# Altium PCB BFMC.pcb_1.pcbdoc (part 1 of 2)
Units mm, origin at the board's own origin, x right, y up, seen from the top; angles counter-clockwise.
Board outline 115.66 x 88.65 mm, 2 copper layers (Top Layer, Bottom Layer); 106 components, 51 nets, 277 pads, 103 vias.
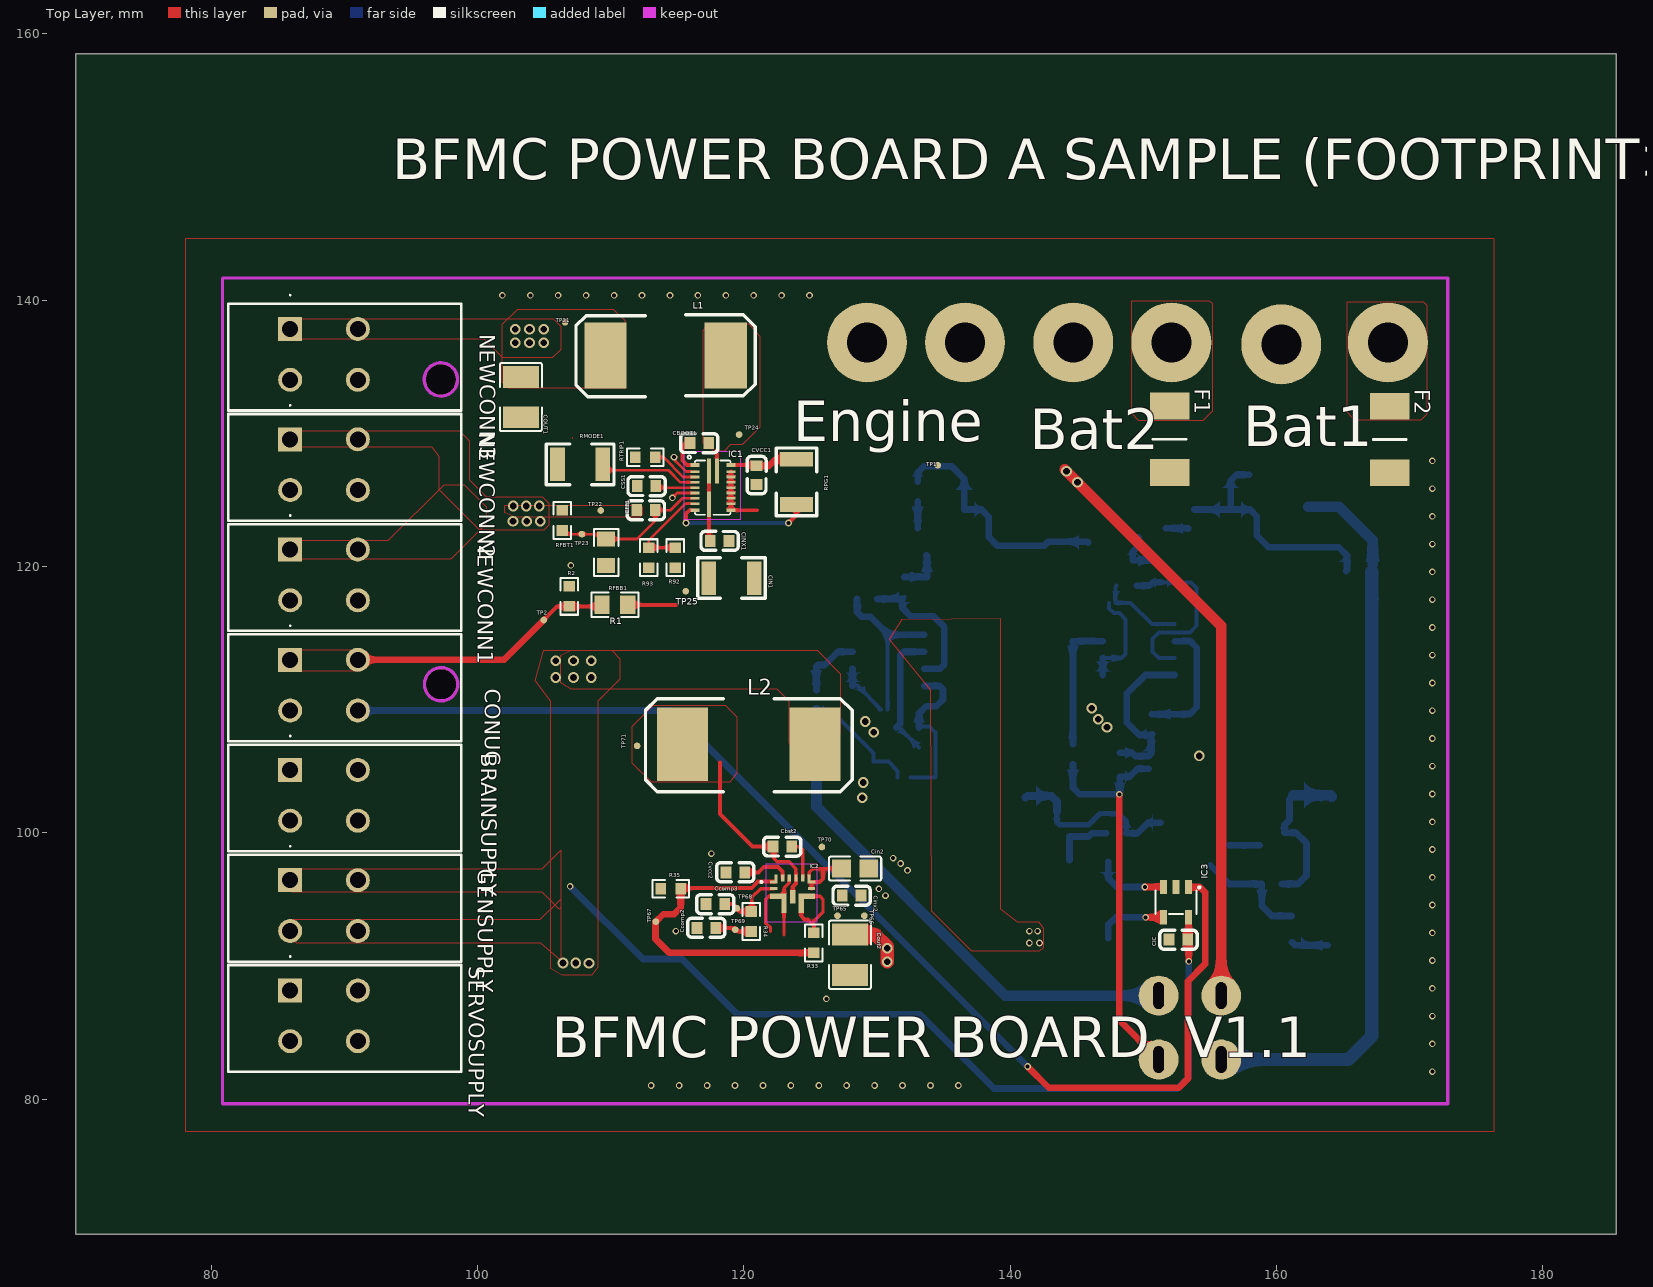
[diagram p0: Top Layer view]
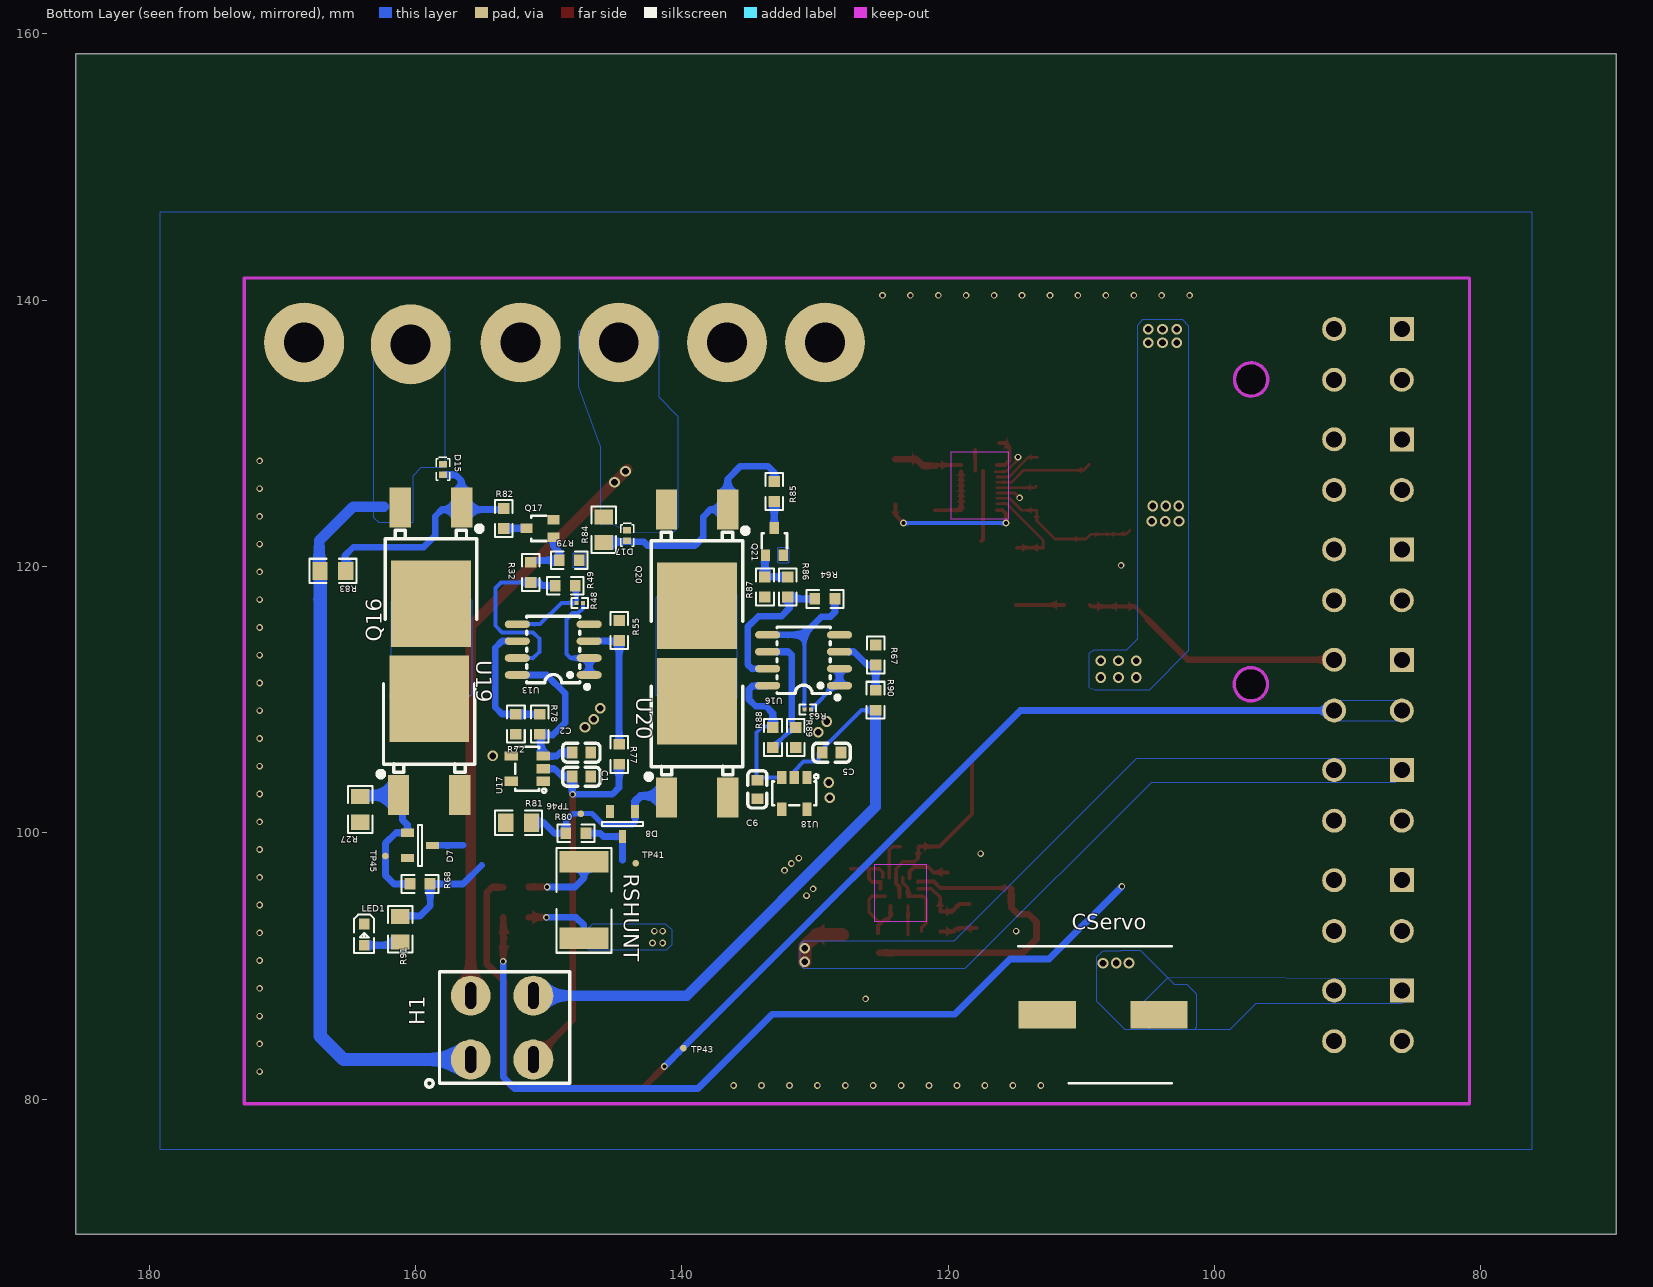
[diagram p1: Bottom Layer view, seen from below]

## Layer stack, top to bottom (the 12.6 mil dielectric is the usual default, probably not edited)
Top Layer: signal copper (thickness not stored)
Dielectric: dielectric 0.32, FR-4, Dk 4.8
Bottom Layer: signal copper (thickness not stored)

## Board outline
185.51,69.85 69.85,69.85 69.85,158.498 185.51,158.498
cut-out: 98.509,134.048 ccw(c97.259,134.048) 96.009,134.048 ccw(c97.259,134.048)
cut-out: 98.526,111.161 ccw(c97.276,111.161) 96.026,111.161 ccw(c97.276,111.161)

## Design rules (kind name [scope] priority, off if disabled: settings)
Clearance copperThickness1oz [All] p1: gap=0.178 ignorepadtopadclearanceinfootprint=FALSE except(0.102: Track-Track; 0.152: Track-SMDPad SMDPad-SMDPad Track-THPad SMDPad-THPad THPad-THPad Track-Via SMDPad-Via THPad-Via Via-Via Track-Fill SMDPad-Fill THPad-Fill Via-Fill Fill-Fill SMDPad-Region THPad-Region Via-Region Fill-Region Region-Region Track-Poly SMDPad-Poly THPad-Poly Via-Poly Fill-Poly Poly-Poly Track-Text SMDPad-Text THPad-Text Via-Text Fill-Text Region-Text Poly-Text Text-Text Track-Hole SMDPad-Hole THPad-Hole Via-Hole Fill-Hole Region-Hole Poly-Hole Text-Hole; 0.3: Track-Region Region-Poly Track-Sheet SMDPad-Sheet THPad-Sheet Via-Sheet Fill-Sheet Region-Sheet Poly-Sheet Text-Sheet Sheet-Hole)
Clearance copperThickness2oz [All] p1: gap=0.178 ignorepadtopadclearanceinfootprint=FALSE except(0.152: Track-SMDPad SMDPad-SMDPad Track-THPad SMDPad-THPad THPad-THPad Track-Via SMDPad-Via THPad-Via Via-Via Track-Fill SMDPad-Fill THPad-Fill Via-Fill Fill-Fill SMDPad-Region THPad-Region Via-Region Fill-Region Region-Region Track-Poly SMDPad-Poly THPad-Poly Via-Poly Fill-Poly Poly-Poly Track-Text SMDPad-Text THPad-Text Via-Text Fill-Text Region-Text Poly-Text Text-Text Track-Hole SMDPad-Hole THPad-Hole Via-Hole Fill-Hole Region-Hole Poly-Hole Text-Hole; 0.203: Track-Track; 0.3: Track-Region Region-Poly Track-Sheet SMDPad-Sheet THPad-Sheet Via-Sheet Fill-Sheet Region-Sheet Poly-Sheet Text-Sheet Sheet-Hole)
Clearance Supply-GND [All] p1: gap=0.178 ignorepadtopadclearanceinfootprint=FALSE except(0.5: Track-Track Track-SMDPad SMDPad-SMDPad Track-THPad SMDPad-THPad THPad-THPad Track-Via SMDPad-Via THPad-Via Via-Via Track-Fill SMDPad-Fill THPad-Fill Via-Fill Fill-Fill Track-Region SMDPad-Region THPad-Region Via-Region Fill-Region Region-Region Track-Poly SMDPad-Poly THPad-Poly Via-Poly Fill-Poly Region-Poly Poly-Poly Track-Text SMDPad-Text THPad-Text Via-Text Fill-Text Region-Text Poly-Text Text-Text Track-Sheet SMDPad-Sheet THPad-Sheet Via-Sheet Fill-Sheet Region-Sheet Poly-Sheet Text-Sheet Track-Hole SMDPad-Hole THPad-Hole Via-Hole Fill-Hole Region-Hole Poly-Hole Text-Hole Sheet-Hole)
DiffPairsRouting differentialPair [All] p1: maxuncoupledlength=10 maxlimit=5.9843 mostfreqgap=5.9843 toplayer_minwidth=5 toplayer_prefwidth=10 toplayer_maxwidth=100 bottomlayer_minwidth=5 bottomlayer_prefwidth=10 bottomlayer_maxwidth=100
PasteMaskExpansion pasteMaskExpansion [All] p1:
PlaneConnect innerPlane [All] p1: planeconnectstyle=Relief reliefexpansion=0.508 reliefentries=4 reliefconductorwidth=0.254 reliefairgap=0.254
PolygonConnect copperRegion [All] p1: connectstyle=Direct reliefentries=4 reliefconductorwidth=10 polygonreliefangle="90 Angle" airgapwidth=10
PolygonConnect copperRegion1 [All] p1: connectstyle=Relief reliefentries=4 reliefconductorwidth=10 polygonreliefangle="90 Angle" airgapwidth=10
PolygonConnect copperRegion2 [All] p1: connectstyle=Relief reliefentries=4 reliefconductorwidth=10 polygonreliefangle="90 Angle" airgapwidth=10
RoutingVias viaSize [All] p1: viastyle="Through Hole" holewidth=12.0078 minholewidth=11.811 maxholewidth=248.0314 width=24.0158 minwidth=19.685 maxwidth=393.7008
SolderMaskExpansion solderMaskExpansion [All] p1: useseparateexpansions=TRUE expansion=2.0079 expansionbottom=2.0079
Width copperThickness1oz [All] p1: maxlimit=100 minlimit=5 preferedwidth=10
Width copperThickness2oz [All] p1: maxlimit=100 minlimit=8 preferedwidth=10

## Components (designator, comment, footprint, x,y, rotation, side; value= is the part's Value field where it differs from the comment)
BRAINSUPPLY "switch" 1704498 85.944,104.723 r270 top
C1 "CAP_0201" C0603 147.54,104.22 r180 bottom
C2 "CAP_0201" C0603 147.54,106.02 r180 bottom
C5 "CAP_0201" C0603 128.76,106.02 r180 bottom
C6 "CAP_0201" C0603 134.34,103.26 r270 bottom
CBOOT1 "EMK105 B7104KVHF" C0603 116.664,129.265 r0 top
Cbst2 "CAP_0201" C0603 122.903,98.97 r0 top
Ccomp2 "CAP_0201" C0603 117.188,92.874 r0 top
Ccomp3 "CAP_0201" C0603 117.871,94.644 r0 top
CFF1 "C1005C0G1H220J" C0603 112.662,124.229 r0 top
CIC "C2012X7S1C106K" C0603 152.64,91.98 r180 top
CIN1 "GCJ31CC71E106K" R1206-1 119.086,119.132 r0 top
Cin2 "CAP_0201" c0805 128.364,97.319 r180 top
CINX1 "GCM188C71A225K" C0603 118.197,121.926 r0 top
Cinx2 "CAP_0201" C0603 128.11,95.287 r0 top
CONUC "switch" 1704498 85.944,113 r270 top
COUT1 "EMK325ABJ107MM-T" C1210 103.264,132.725 r270 top
Cout2 "CAP_0201" C1210 127.971,90.844 r90 top
CServo "GCM188C71A225K" CAPAE1030X1050N 108.377,86.347 r180 bottom
CSS1 "C1608X7R1H154K" C0603 112.697,126.041 r180 top
CVCC1 "GCM188C71A225K" C0603 120.964,126.865 r270 top
Cvcc2 "CAP_0201" C0603 119.371,97.044 r0 top
D7 "SZBZX84C18ET1G" SZBZX84C18ET1G 159.664,99.065 r270 bottom
D8 "SZBZX84C18ET1G" SZBZX84C18ET1G 144.464,100.665 r0 bottom
D15 "PZU6.8B2L,315" DFN1006-2L-RD 157.953,127.29 r270 bottom
D17 "PZU6.8B2L,315" DFN1006-2L-RD 144.11,122.337 r270 bottom
F1 "0451015.MRL" FUSC6127X294N 151.984,129.568 r270 top
F2 "0451015.MRL" FUSC6127X294N 168.512,129.541 r270 top
GENSUPPLY "switch" 1704498 85.944,96.447 r270 top
H1 "switch" M2021BB1W01 153.508,85.38 r0 bottom
IC1 "TPS548A28RWWR" TPS548B28RWWR 117.689,125.928 r0 top
IC2 "TPS61288RQQR" TPS61288RQQR 123.671,95.444 r0 top
IC3 "INA180A2QDBVRQ1" ina180a2qdbvrq1 152.46,94.8 r180 top
L1 "IHLP4040DZERR47M11" IHLP4040DZERR47M11 114.133,135.799 r0 top
L2 "L_0402" "dr127-3r3-r (l2)" 120.371,106.657 r0 top
LED1 "19-213/Y2C-CQ2R2L/3T(CY)" LED0603-RD-YELLOW 163.864,92.365 r270 bottom
NEWCONN1 "switch" 1704498 85.944,121.277 r270 top
NEWCONN2 "switch" 1704498 85.944,129.554 r270 top
NEWCONN3 "switch" 1704498 85.944,137.831 r270 top
Q16 "IPD50P04P4-13" pg-to252-3_l6.3-w6.5-p4.57-ls10.0-br-cw 158.842,120.813 r90 bottom
Q17 "BC846W" SOT-323-3_L2.2-W1.3-P1.30-LS2.2-BR 150.664,122.865 r180 bottom
Q20 "IPD50P04P4-13" pg-to252-3_l6.3-w6.5-p4.57-ls10.0-br-cw 138.864,120.665 r90 bottom
Q21 "BC846W" SOT-323-3_L2.2-W1.3-P1.30-LS2.2-BR 133.064,121.865 r270 bottom
R1 "MCR03..PFX1051" R0805_NEW 110.328,117.13 r0 top
R2 "MCR03...PFX7680" r0603_new 106.899,117.765 r90 top
R27 "MCR03..PFX1002" R0805_NEW 164.164,101.765 r270 bottom
R32 "MCR03..PFX1002" R0603 151.364,119.565 r90 bottom
R33 "MCR03..PFX1002" R0603 125.271,91.744 r90 top
R34 "MCR03..PFX1002" R0603 120.571,93.344 r90 top
R35 "MCR03..PFX1002" R0603 114.521,95.795 r180 top
R48 "Res_0603" R0201 147.664,117.265 r0 bottom
R49 "Res_0603" R0603 148.764,118.565 r0 bottom
R55 "Res_0603" R0603 144.72,115.2 r270 bottom
R63 "Res_0603" R0201 130.564,109.265 r0 bottom
R64 "Res_0603" R0603 129.264,117.565 r0 bottom
R67 "Res_0603" R0603 125.437,113.365 r270 bottom
R68 "Res_0603" R0603 159.664,96.165 r180 bottom
R72 "Res_0603" R0603 152.464,108.165 r270 bottom
R77 "Res_0603" R0603 144.72,105.9 r270 bottom
R78 "Res_0603" R0603 150.664,108.165 r270 bottom
R79 "Res_0603" R0603 148.464,120.465 r0 bottom
R80 "Res_0603" R0603 147.964,99.965 r180 bottom
R81 "MCR03..PFX1002" R0805_NEW 152.264,100.765 r0 bottom
R82 "Res_0603" R0603 153.381,123.607 r90 bottom
R83 "MCR03..PFX1002" R0805_NEW 166.208,119.67 r0 bottom
R84 "MCR03..PFX1002" R0805_NEW 145.864,122.765 r90 bottom
R85 "Res_0603" R0603 133.061,125.639 r90 bottom
R86 "MCR03..PFX1002" R0603 132.064,118.465 r270 bottom
R87 "Res_0603" R0603 133.764,118.465 r90 bottom
R88 "Res_0603" R0603 133.164,107.165 r270 bottom
R89 "Res_0603" R0603 131.464,107.165 r270 bottom
R90 "Res_0603" R0603 125.464,109.965 r90 bottom
R91 "Res_0603" R0805_NEW 161.164,92.765 r90 bottom
R92 "Res_0603" R0603 114.864,120.665 r270 top
R93 "Res_0603" R0603 112.864,120.665 r90 top
RFBB1 "SMM0204 50 10K 1 %" R0805 109.664,121.065 r270 top
RFBT1 "SMM0204 50 73K2 1 %" R0603 106.364,123.465 r270 top
RMODE1 "SMM0204 50 30K1 1 %" R1206-1 107.715,127.677 r180 top
RPG1 "SMM0204 50 30K1 1 %" R1206-1 123.964,126.365 r90 top
RSHUNT "WSLP25122L500FEA" "WSLP25122L000FEA BUN" 147.364,94.965 r270 bottom
RTRIP1 "SMM0204 50 7K32 1 %" R0603 112.606,128.214 r180 top
SERVOSUPPLY "switch" 1704498 85.944,88.17 r270 top
TP1 "Test-Point" Test-Point-0.5mm 134.569,127.607 r180 top
TP2 "Test-Point" Test-Point-0.5mm 104.98,115.987 r0 top
TP21 "Test-Point" Test-Point-0.5mm 106.588,138.349 r0 top
TP22 "Test-Point" Test-Point-0.5mm 109.268,124.212 r0 top
TP23 "Test-Point" Test-Point-0.5mm 107.847,122.434 r90 top
TP24 "Test-Point" Test-Point-0.5mm 119.651,129.911 r270 top
TP25 "Test-Point" Test-Point-0.5mm 115.651,118.146 r0 top
TP41 "Test-Point" Test-Point-0.5mm 143.472,97.723 r180 bottom
TP43 "Test-Point" Test-Point-0.5mm 139.89,83.841 r180 bottom
TP45 "Test-Point" Test-Point-0.5mm 162.264,98.265 r180 bottom
TP46 "Test-Point" Test-Point-0.5mm 147.591,101.439 r180 bottom
TP65 "Test-Point" Test-Point-0.5mm 127.039,93.784 r0 top
TP66 "Test-Point" Test-Point-0.5mm 129.062,93.782 r270 top
TP67 "Test-Point" Test-Point-0.5mm 113.401,93.335 r0 top
TP68 "Test-Point" Test-Point-0.5mm 119.486,94.335 r0 top
TP69 "Test-Point" Test-Point-0.5mm 119.364,92.733 r0 top
TP70 "Test-Point" Test-Point-0.5mm 125.871,98.944 r270 top
TP71 "Test-Point" Test-Point-0.5mm 111.994,106.536 r0 top
U13 "LT1490IS8#PBF" SO-8_L4.9-W3.9-P1.27-LS5.9-BL 149.664,113.765 r90 bottom
U16 "LT1490IS8#PBF" SO-8_L4.9-W3.9-P1.27-LS5.9-BL 130.864,112.965 r90 bottom
U17 "NCP715SN50T1G" TSOP-5_L3.0-W1.5-P0.95-BL 151.62,104.82 r90 bottom
U18 "NCP715SN50T1G" TSOP-5_L3.0-W1.5-P0.95-BL 131.564,102.965 r0 bottom
U19 "DMPH3010LK3-13" pg-to252-3_l6.3-w6.5-p4.57-ls10.0-br-cw 158.978,106.451 r270 bottom
U20 "DMPH3010LK3-13" pg-to252-3_l6.3-w6.5-p4.57-ls10.0-br-cw 138.864,106.265 r270 bottom

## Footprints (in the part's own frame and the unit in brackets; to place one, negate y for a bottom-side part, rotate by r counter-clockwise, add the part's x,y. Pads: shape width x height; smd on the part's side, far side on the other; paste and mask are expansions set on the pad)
1704498 [mm]
  rect 1.8x1.8 hole 1.2: 1(0,0)
  round 1.8 hole 1.2: 2(0,5.08) 3(3.81,0) 4(3.81,5.08)
  silkscreen extent -2.6,-4.65 6.11,12.85
C0603 [mm]
  rect 0.8x0.9 smd: 1(-0.7,0) 2(0.7,0)
  silkscreen extent -1.41,-0.71 1.39,0.72
c0805 [mm]
  rect 1.41x1.35 smd: 1(-1.03,0) 2(1.03,0)
  silkscreen extent -1.96,-0.9 1.96,0.9
C1210 [mm]
  rect 1.635x2.7 smd: 1(-1.517,0) 2(1.517,0)
  silkscreen extent -2.56,-1.58 2.56,1.58
CAPAE1030X1050N [mm]
  rect 4.3x2.05 smd: 1(-4.2,0) 2(4.2,0)
  silkscreen extent -6.35,-5.15 5.15,5.15
DFN1006-2L-RD [mm]
  rect 0.5x0.6 smd: 1(-0.4,0) 2(0.4,0)
  silkscreen extent -0.9,-0.5 0.8,0.5
"dr127-3r3-r (l2)" [mm]
  rect 3.85x5.5 smd: 1(-4.975,0) 2(4.975,0)
  silkscreen extent -7.75,-3.56 7.77,3.43
FUSC6127X294N [mm]
  rect 2.02x2.95 smd: 1(-2.5,0) 2(2.5,0)
  silkscreen extent 0,-1.24 0,1.24
IHLP4040DZERR47M11 [mil]
  rect 125x195 smd: 1(-177.5,2.5) 2(177.5,2.5)
  silkscreen extent -265,-120 265,122
ina180a2qdbvrq1 [mm]
  rect 0.532x1.07 smd: 1(-0.95,-1.135) 2(0,-1.135) 3(0.95,-1.135) 4(0.95,1.135) 5(-0.95,1.135)
  silkscreen extent -1.9,-1.25 1.53,0.88
LED0603-RD-YELLOW [mm]
  rect 0.8x0.8 smd: 1(-0.799,-0.003) 2(0.799,0.003)
  silkscreen extent -1.49,-0.75 1.39,0.76
M2021BB1W01 [mm]
  round 3 hole 0.8 slot 2 at 90 deg: 1(-2.35,-2.4) 2(2.35,-2.4) 3(-2.35,2.4) 4(2.35,2.4)
  silkscreen extent -5.08,-4.19 5.74,4.47
pg-to252-3_l6.3-w6.5-p4.57-ls10.0-br-cw [mm]
  rect 3x1.6 smd: 1(3.614,-2.299) 3(3.614,2.299)
  rect 6.5x6 smd: 2(-3.614,0.001)
  silkscreen extent -4.76,-3.83 2.24,3.43
R0201 [mm]
  rect 0.303x0.324 smd: 1(-0.242,0) 2(0.242,0)
  silkscreen extent -0.62,-0.39 0.62,0.39
R0603 [mm]
  rect 0.806x0.864 smd: 1(-0.753,0) 2(0.753,0)
  silkscreen extent -1.39,-0.66 1.39,0.66
r0603_new [mm]
  rect 0.806x0.864 smd: 1(-0.753,0) 2(0.753,0)
  silkscreen extent -1.39,-0.66 1.39,0.66
R0805 [mm]
  rect 1.133x1.377 smd: 1(-1,0) 2(1,0)
  silkscreen extent -1.76,-0.92 1.76,0.92
R0805_NEW [mm]
  rect 1.133x1.377 smd: 1(-0.966,0) 2(0.966,0)
  silkscreen extent -1.76,-0.92 1.76,0.92
R1206-1 [mm]
  rect 1.1x2.5 smd: 1(-1.7,0) 2(1.7,0)
  silkscreen extent -2.54,-1.52 2.54,1.52
SO-8_L4.9-W3.9-P1.27-LS5.9-BL [mm]
  oval 0.574x1.888 smd: 1(-1.905,-2.699) 2(-0.635,-2.699) 3(0.635,-2.699) 4(1.905,-2.699) 5(1.905,2.699) 6(0.635,2.699) 7(-0.635,2.699) 8(-1.905,2.699)
  silkscreen extent -2.94,-2.69 2.5,2
SOT-323-3_L2.2-W1.3-P1.30-LS2.2-BR [mm]
  rect 0.9x0.7 smd: 1(1.016,-0.66) 2(1.016,0.66) 3(-1.016,0)
  silkscreen extent -0.65,-0.95 0.48,0.95
SZBZX84C18ET1G [mm]
  rect 0.61x0.975 smd: 1(-0.95,-0.937) 2(0.95,-0.937)
  rect 0.523x0.975 smd: 3(0,0.937)
  silkscreen extent -1.54,-0.14 1.54,0.14
Test-Point-0.5mm [mm]
  round 0.5 smd: 1(0,0)
TPS548B28RWWR [mm]
  rect 0.7x0.3 smd: 1(-1.35,1.7) 9(-1.35,-1.7) 11(1.35,-1.7) 19(1.35,1.7)
  rect 0.7x0.2 smd: 2(-1.35,1.2) 3(-1.35,0.8) 4(-1.35,0.4) 5(-1.35,0) 6(-1.35,-0.4) 7(-1.35,-0.8) 8(-1.35,-1.2) 12(1.35,-1.2) 13(1.35,-0.8) 14(1.35,-0.4) 15(1.35,0) 16(1.35,0.4) 17(1.35,0.8) 18(1.35,1.2)
  rect 0.3x1.9 smd: 10(-0.3,-1.25) 20(0.3,1.25) 21(-0.3,1.25)
  silkscreen extent -1.9,-2.03 1.32,2.41
TPS61288RQQR [mm]
  rect 0.575x0.25 smd: 1(-1.413,0.875) 7(1.413,0.875)
  rect 0.55x0.25 smd: 2(-1.425,0.375) 6(1.425,0.375)
  rect 1.25x0.4 smd: 3(-1.075,-0.2) 5(1.075,-0.2)
  rect 0.4x1 smd: 4(0,-0.25)
  rect 0.25x0.55 smd: 8(0.75,1.175) 9(0.25,1.175) 10(-0.25,1.175) 11(-0.75,1.175)
  rect 0.225x0.45 smd: 12(-1.237,1.225) 15(1.237,1.225)
  rect 0.4x1.05 smd: 13(-0.65,-0.925) 14(0.65,-0.925)
  silkscreen extent -2.4,0.83 -2.3,0.92
TSOP-5_L3.0-W1.5-P0.95-BL [mm]
  rect 0.7x1 smd: 1(-0.95,-1.2) 2(0,-1.2) 3(0.95,-1.2) 4(0.95,1.2) 5(-0.95,1.2)
  silkscreen extent -1.8,-1.42 1.65,0.89
"WSLP25122L000FEA BUN" [mm]
  rect 1.6x3.68 smd: 1(-2.875,0) 2(2.875,0)
  silkscreen extent -3.91,-2.07 3.96,2.07

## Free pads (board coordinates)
  round 6 hole 3: 22(129.251,136.815) 22(136.617,136.815) 22(144.745,136.815) 22(152.111,136.815) 22(160.366,136.688) 22(168.367,136.815)

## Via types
v1: diameter 0.5, hole 0.3, Top Layer to Bottom Layer, 70 vias
v2: diameter 0.8, hole 0.5, Top Layer to Bottom Layer, 33 vias

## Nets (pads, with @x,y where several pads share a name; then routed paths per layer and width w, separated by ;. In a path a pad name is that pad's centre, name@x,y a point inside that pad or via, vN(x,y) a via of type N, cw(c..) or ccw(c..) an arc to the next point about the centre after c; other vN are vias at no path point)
$1N1788: D8.1 R80.1 R81.1 TP46.1 U20.1 | length 13.8
  Bottom Layer w0.4: D8.1@143.514,101.602 143.514,100.806 143.7,100.62 145.92,100.62 146.762,101.462 147.567,101.462 TP46.1@147.591,101.439 148.161,101.439 148.717,100.883 R80.1@148.717,99.965
  Bottom Layer w0.5: R80.1@148.717,99.965 149.551,99.965 150.351,100.765 R81.1@151.297,100.765
  Bottom Layer w0.6: U20.1@141.163,102.651 141.292,102.78 143.1,102.78 143.514,102.366 D8.1@143.514,101.602
$1N1798: D7.1 R27.1 R68.1 TP45.1 U19.1 | length 12.6
  Bottom Layer w0.5: R68.1@160.417,96.165 161.626,96.165 162.264,96.803 TP45.1@162.264,98.265 162.264,99.23 161.479,100.015 D7.1@160.601,100.015 160.601,100.601 160.978,100.978 160.978,102.537 U19.1@161.278,102.837
  Bottom Layer w0.8: U19.1@161.278,102.837 164.057,102.837 R27.1@164.164,102.731
$1N2164: Q16.2 U19.2
$1N2337: D15.2 Q16.1 R82.2 R83.1 | length 18.5
  Bottom Layer w0.5: 153.824,124.279 158.021,124.279 158.52,123.78 158.52,122.323 159.395,121.448 164.684,121.448 165.297,120.834 165.297,119.726 R83.1@165.241,119.67 ; Q16.1@156.542,124.427 156.564,124.449 156.564,126.444 157.01,126.89 D15.2@157.953,126.89
$1N2412: Q17.3 R82.1 | length 1.7
  Bottom Layer w0.5: Q17.3@151.68,122.865 153.369,122.865 R82.1@153.381,122.853
$1N2516: Q17.1 R32.2 R79.2 | length 4
  Bottom Layer w0.5: Q17.1@149.648,122.204 149.648,121.549 149.217,121.118 R79.2@149.217,120.465 151.117,120.465 R32.2@151.264,120.318
$1N20674: R55.2 R77.1 U13.3 | length 10
  Bottom Layer w0.5: R77.1@144.72,106.653 144.72,114.387 144.733,114.4 U13.3@146.965,114.4
$1N20931: R48.1 U13.1 U13.2 | length 7.7
  Bottom Layer w0.3: U13.2@146.965,113.13 148.382,113.13 148.682,113.43 148.682,116.03 148.217,116.495 147.793,116.495 147.422,116.865 R48.1@147.422,117.265
  Bottom Layer w0.5: U13.1@146.965,111.86 U13.2@146.965,113.13
$1N20946: R48.2 R49.1 U13.5 | length 6.5
  Bottom Layer w0.3: R49.1@148.01,118.565 147.905,118.46 R48.2@147.905,117.265 149.055,117.265 150.65,115.67 U13.5@152.363,115.67
$1N20962: R32.1 R49.2 U13.7 | length 14.2
  Bottom Layer w0.3: R32.1@151.364,118.811 153.604,118.811 154.016,118.4 154.016,115.556 153.525,115.065 151.183,115.065 150.714,114.595 150.714,113.589 151.173,113.13 U13.7@152.363,113.13
  Bottom Layer w0.5: R49.2@149.517,118.565 150.464,118.565 150.71,118.811 R32.1@151.364,118.811
$1N21052: R72.1 R78.1 U13.6 | length 9.9
  Bottom Layer w0.5: R78.1@150.664,108.918 R72.1@152.464,108.918 153.498,108.918 154.02,109.44 154.02,113.9 153.52,114.4 U13.6@152.363,114.4
$1N27791: Q20.2 U20.2
$1N27792: D17.2 Q20.1 R84.1 R85.2 | length 18.5
  Bottom Layer w0.5: R85.2@133.061,126.392 133.061,127.044 133.561,127.544 135.601,127.544 136.564,126.58 Q20.1@136.564,124.279 137.85,124.279 138.395,123.734 138.395,122.21 139.03,121.575 142.586,121.575 142.886,121.875 145.787,121.875 R84.1@145.864,121.799
$1N27793: Q21.3 R85.1 | length 2
  Bottom Layer w0.5: R85.1@133.061,124.885 133.064,124.882 Q21.3@133.064,122.881
$1N27799: Q21.1 R86.1 R87.2 | length 3.3
  Bottom Layer w0.5: R86.1@132.064,119.218 R87.2@133.764,119.218 133.764,120.809 Q21.1@133.724,120.849
$1N27802: R63.1 U16.1 U16.2 | length 4.2
  Bottom Layer w0.3: U16.1@128.165,111.06 128.527,111.06 R63.1@130.322,109.265
  Bottom Layer w0.5: U16.1@128.165,111.06 U16.2@128.165,112.33
$1N27807: R63.2 R64.1 U16.5 | length 12.3
  Bottom Layer w0.3: R63.2@130.805,109.265 130.805,114.865 ; U16.5@133.558,114.865 U16.5@133.563,114.87
  Bottom Layer w0.5: R64.1@128.51,117.565 128.51,116.59 128.88,116.22 129.54,116.22 130.89,114.87 U16.5@133.563,114.87
$1N27811: R64.2 R86.2 U16.7 | length 11
  Bottom Layer w0.3: R86.2@131.917,117.565 R86.2@132.064,117.711
  Bottom Layer w0.5: R64.2@130.017,117.565 131.917,117.565 131.912,117.56 131.912,116.881 132.529,116.265 134.264,116.265 135.064,115.465 135.064,112.656 134.738,112.33 U16.7@133.563,112.33
$1N27822: R67.2 R90.2 U16.3 | length 4.9
  Bottom Layer w0.3: R67.2@125.464,112.511 R67.2@125.564,112.611
  Bottom Layer w0.5: R90.2@125.464,110.718 R67.2@125.464,112.511 ; R67.2@125.564,112.611 126.082,112.611 127.071,113.6 U16.3@128.165,113.6
$1N32332: R88.2 R89.1 U16.6 | length 9.8
  Bottom Layer w0.3: R89.1@131.464,107.918 131.657,107.918 R88.2@133.164,106.411
  Bottom Layer w0.5: R89.1@131.464,107.918 131.764,108.218 131.764,113.365 131.999,113.6 U16.6@133.563,113.6
$1N40141: LED1.2 R91.1 | length 2.8
  Bottom Layer w0.5: R91.1@161.164,91.799 161.397,91.565 LED1.2@163.86,91.565
$2N28: F1.1 pad.22@152.111,136.815
$2N30: F2.1 pad.22@168.367,136.815
$3N2936: Ccomp2.2 R34.1 TP69.1 | length 2.8
  Top Layer w0.3: Ccomp2.2@117.888,92.874 117.902,92.86 119.283,92.86 119.552,92.59 R34.1@120.571,92.59
+5V: CFF1.1 CIC.1 Cin2.2 Cinx2.1 COUT1.1 CServo.2 GENSUPPLY.1 GENSUPPLY.2 GENSUPPLY.3 GENSUPPLY.4 IC2.6 IC2.7 IC2.15 IC3.5 L1.1 L2.2 NEWCONN1.1 NEWCONN1.2 NEWCONN2.1 NEWCONN2.2 NEWCONN3.1 NEWCONN3.2 RFBT1.1 SERVOSUPPLY.1 SERVOSUPPLY.2 TP21.1 TP22.1 TP70.1 | length 70.2
  Top Layer w0.254: IC2.15@124.908,96.669 124.908,97.038 125.189,97.319 Cin2.2@127.334,97.319
  Top Layer w0.3: IC2.7@125.084,96.319 IC2.7@125.096,96.307 ; IC2.6@125.096,95.819 IC2.7@125.096,96.307 ; 125.935,97.25 125.941,97.244 125.941,96.557 125.691,96.307 IC2.7@125.096,96.307
  Top Layer w0.5: IC3.5@153.41,93.665 153.41,92.17 153.34,92.1 153.42,92.02 v1(153.42,90.36)
  Bottom Layer w0.5: v1(106.963,95.985) 112.423,90.525 115.369,90.525 119.521,86.373 133.23,86.373 138.799,80.805 152.563,80.805 153.42,81.661 v1(153.42,90.36)
  other v2: 106.423,90.225 107.38,90.225 108.377,90.211 105.883,111.669 107.216,111.669 108.55,111.669 105.883,112.939 107.216,112.939 108.55,112.939 102.677,123.393 103.705,123.393 104.732,123.393 102.695,124.547 103.674,124.547 104.654,124.547 102.835,136.815 103.914,136.815 104.994,136.815 102.835,137.831 103.914,137.831 104.994,137.831
+VCC2: C2.1 R78.2 U13.8 U17.3 | length 12.6
  Bottom Layer w0.5: C2.1@148.24,106.02 149.16,106.02 149.41,105.77 U17.3@150.42,105.77 150.603,105.953 R78.2@150.603,107.351 ; R78.2@150.664,107.411 R78.2@150.603,107.351 ; U13.8@152.363,111.86 150.159,111.86 148.764,110.465 148.764,108.285 149.698,107.351 R78.2@150.603,107.351
+VCC3: C6.1 R88.1 U16.8 U18.3 | length 12.3
  Bottom Layer w0.3: U18.3@132.514,104.165 134.382,104.165 134.382,107.553 133.95,107.986 133.231,107.986 R88.1@133.164,107.918
  Bottom Layer w0.5: R88.1@133.164,107.918 133.164,108.978 133.696,109.51 134.458,109.51 134.966,110.018 134.966,110.78 134.712,111.034 133.589,111.034 U16.8@133.563,111.06
ADC1: CONUC.1 CONUC.2 R1.1 R2.1 TP2.1 | length 20
  Top Layer w0.3: TP2.1@104.98,115.987 105.996,117.003 109.234,117.003 R1.1@109.361,117.13
  Top Layer w0.5: CONUC.2@91.024,113 101.993,113 TP2.1@104.98,115.987
BOOT: CBOOT1.1 IC1.1 | length 2.9
  Top Layer w0.3: CBOOT1.1@116.164,129.265 115.739,129.265 115.403,128.928 115.403,127.96 115.735,127.628 IC1.1@116.339,127.628
BST: Cbst2.2 IC2.8 | length 3
  Top Layer w0.254: Cbst2.2@123.603,98.97 124.173,98.97 124.421,98.722 IC2.8@124.421,96.619
COMP: Ccomp3.2 IC2.2 R34.2 TP68.1 | length 5.4
  Top Layer w0.254: R34.2@120.571,94.097 120.615,94.141 120.615,95.159 121.275,95.819 IC2.2@122.246,95.819
  Top Layer w0.3: Ccomp3.2@118.416,94.644 119.171,94.644 119.717,94.097 R34.2@120.571,94.097
EN: IC1.8 R92.1 R93.2 | length 7.2
  Top Layer w0.2: R93.2@112.864,121.418 112.864,121.965 115.627,124.728 IC1.8@116.339,124.728
  Top Layer w0.254: R93.2@112.864,121.418 R92.1@114.864,121.418
FB: CFF1.2 IC1.7 RFBB1.1 RFBT1.2 TP23.1 | length 12
  Top Layer w0.2: RFBT1.2@106.364,122.711 106.641,122.434 TP23.1@107.847,122.434 109.295,122.434 RFBB1.1@109.664,122.065 111.985,122.065 113.362,123.442 CFF1.2@113.362,124.229 114.509,124.229 115.408,125.128 IC1.7@116.339,125.128
FB_1: IC2.1 IC2.12 R33.1 R35.1 TP67.1 | length 24.5
  Top Layer w0.3: R35.1@115.274,95.795 115.323,95.844 120.571,95.844 121.071,96.344 122.233,96.344 IC2.1@122.258,96.319
  Top Layer w0.5: R35.1@115.274,95.795 115.274,94.389 114.775,93.89 113.956,93.89 TP67.1@113.401,93.335 113.378,93.312 113.378,92.036 114.424,90.99 R33.1@125.171,90.99
GND: 
ISHUNT: CONUC.3 CONUC.4 IC3.1 TP43.1 | length 90.3
  Top Layer w0.5: v1(141.316,82.459) 142.91,80.865 152.676,80.865 153.364,81.553 153.364,88.864 154.651,90.151 154.651,95.54 154.278,95.913 IC3.1@153.432,95.913
  Bottom Layer w0.3: TP43.1@139.89,83.841 TP43.1@139.933,83.841
  Bottom Layer w0.5: CONUC.4@91.024,109.19 114.584,109.19 139.933,83.841 v1(141.316,82.459)
MODE: IC1.4 RMODE1.1 | length 7.5
  Top Layer w0.2: RMODE1.1@109.415,127.677 109.86,127.232 114.352,127.232 115.257,126.328 IC1.4@116.339,126.328
OUT_BATT: CIN1.1 CINX1.1 IC1.10 IC1.21 IC3.4 pad.22@136.617,136.815 R1.2 R92.2 RSHUNT.2 TP1.1 TP25.1 | length 14.3
  Top Layer w0.3: R1.2@111.294,117.13 114.9,117.13 ; IC1.21@117.389,127.178 IC1.10@117.389,124.678 117.389,122.034 CINX1.1@117.496,121.926
  Top Layer w0.5: v1(150.18,93.66) 151.505,93.66 IC3.4@151.51,93.665
  Bottom Layer w0.5: RSHUNT.2@147.364,92.09 147.364,93.079 147.945,93.66 v1(150.18,93.66)
  other v1: 141.443,91.73 142.205,91.73 141.443,92.619 142.078,92.619
OUT_BATT1: D15.1 H1.4 pad.22@160.366,136.688 Q16.3 R83.2 | length 54.6
  Bottom Layer w0.8: 162.398,124.496 164.693,124.496 167.23,121.959 R83.2@167.23,120.165
  Bottom Layer w1: H1.4@155.858,82.98 165.407,82.98 167.171,84.744 R83.2@167.171,119.607
OUT_BATT2: D17.1 H1.2 pad.22@144.745,136.815 Q20.3 R84.2 | length 44.4
  Top Layer w0.8: v2@144.11,127.29 v2(145.064,126.336) 155.858,115.542 H1.2@155.858,87.78
  other v2: 144.237,127.163
PGOOD: IC1.9 RPG1.1 | length 10.8
  Top Layer w0.3: v1@115.657,123.281 115.657,123.974 115.911,124.228 IC1.9@116.339,124.228 ; v1(123.364,123.265) 123.964,123.865 RPG1.1@123.964,124.665
  Bottom Layer w0.3: v1(115.664,123.265) v1(123.364,123.265)
SS_REFIN: CSS1.1 IC1.5 | length 3
  Top Layer w0.2: CSS1.1@113.397,126.041 113.51,125.928 IC1.5@116.339,125.928
SW: CBOOT1.2 IC1.20 L1.2 TP24.1 | length 1.6
  Top Layer w0.254: IC1.20@117.989,127.178 117.989,128.765
SW_1: Cbst2.1 IC2.4 IC2.9 L2.1 TP71.1 | length 14
  Top Layer w0.254: Cbst2.1@122.203,98.97 122.268,98.905 122.268,98.081 122.522,97.827 123.411,97.827 123.921,97.317 IC2.9@123.921,96.619
  Top Layer w0.3: 118.202,105.299 118.202,101.413 120.644,98.97 Cbst2.1@122.203,98.97 ; IC2.4@123.671,95.194 123.671,95.944 123.921,96.194 IC2.9@123.921,96.619
TRIP: IC1.3 RTRIP1.1 | length 3.6
  Top Layer w0.2: RTRIP1.1@113.328,128.194 113.347,128.214 113.971,128.214 115.457,126.728 IC1.3@116.339,126.728
UBATT: D7.3 D8.3 IC3.3 R68.2 R80.2 R91.2 RSHUNT.1 TP41.1 U19.3 U20.3 | length 21.3
  Top Layer w0.5: v1(150.12,95.94) 151.505,95.94 IC3.3@151.51,95.935
  Bottom Layer w0.5: 144.464,97.953 D8.3@144.464,99.727 145.884,99.727 146.122,99.965 R80.2@147.21,99.965 ; RSHUNT.1@147.364,97.84 147.364,96.604 148.027,95.94 v1(150.12,95.94) ; 155.032,97.572 156.439,96.165 R68.2@158.91,96.165 158.91,94.518 159.664,93.765 161.13,93.765 R91.2@161.164,93.731 ; 156.429,99.065 D7.3@158.726,99.065
VBATT1: C1.1 H1.3 R77.2 U17.2 | length 30.3
  Top Layer w0.5: v1(148.2,102.9) 148.2,85.937 H1.3@151.158,82.98
  Bottom Layer w0.5: R77.2@144.72,105.147 144.72,103.4 145.22,102.9 v1(148.2,102.9) 148.24,102.94 C1.1@148.24,104.22 148.98,104.22 149.58,104.82 U17.2@150.42,104.82
VBATT2: C5.1 H1.1 R90.1 U18.2 | length 47.7
  Bottom Layer w0.3: R90.1@125.464,109.211 126.517,109.211 129.738,105.99 129.738,105.365 130.164,105.365 130.864,105.365 131.564,104.665 U18.2@131.564,104.165
  Bottom Layer w0.8: R90.1@125.464,109.211 125.464,101.965 139.649,87.78 H1.1@151.158,87.78
VCC: CVCC1.1 IC1.19 RPG1.2 | length 5.2
  Top Layer w0.3: IC1.19@119.039,127.628 120.901,127.628 CVCC1.1@120.964,127.565
  Top Layer w0.5: CVCC1.1@120.964,127.565 121.907,127.565 122.395,128.053 123.952,128.053 RPG1.2@123.964,128.065
VCCBOOST: Cvcc2.2 IC2.11 | length 3.6
  Top Layer w0.3: Cvcc2.2@120.07,97.044 121.104,97.044 121.504,97.444 122.571,97.444 122.921,97.094 IC2.11@122.921,96.619
VOUT1: BRAINSUPPLY.1 BRAINSUPPLY.2 Cout2.2 IC2.5 IC2.14 R33.2 TP65.1 TP66.1 | length 10.3
  Top Layer w0.254: IC2.5@124.746,95.244 125.737,95.244 125.949,95.032 125.949,94.047 125.108,93.206
  Top Layer w0.3: IC2.14@124.321,94.519 124.321,93.762 124.575,93.508 124.806,93.508 125.108,93.206 125.271,93.043 R33.2@125.271,92.497
  Top Layer w1: Cout2.2@127.971,92.361 129.889,92.361 130.775,91.476 v2(130.775,91.349) v2(130.775,90.333)
pads on no net: BRAINSUPPLY.3 BRAINSUPPLY.4 C1.2 C2.2 C5.2 C6.2 Ccomp2.1 Ccomp3.1 CIC.2 CIN1.2 Cin2.1 CINX1.2 Cinx2.2 COUT1.2 Cout2.1 CServo.1 CSS1.2 CVCC1.2 Cvcc2.1 D7.2 D8.2 F1.2 F2.2 IC1.2 IC1.6 IC1.11 IC1.12 IC1.13 IC1.14 IC1.15 IC1.16 IC1.17 IC1.18 IC2.3 IC2.10 IC2.13 IC3.2 LED1.1 NEWCONN1.3 NEWCONN1.4 NEWCONN2.3 NEWCONN2.4 NEWCONN3.3 NEWCONN3.4 Q17.2 Q21.2 R2.2 R27.2 R35.2 R55.1 R67.1 R72.2 R79.1 R81.2 R87.1 R89.2 R93.1 RFBB1.2 RMODE1.2 RTRIP1.2 SERVOSUPPLY.3 SERVOSUPPLY.4 U13.4 U16.4 U17.1 U17.4 U17.5 U18.1 U18.4 U18.5
copper on no net: | length 16.7
  Top Layer w0.2: v1(114.641,125.166) 115.003,125.528 116.339,125.528 ; v1@114.765,128.212 114.765,128.037 115.674,127.128 116.466,127.128
  Top Layer w0.254: 119.039,124.228 121.003,124.228 ; 122.012,92.619 122.012,92.873 121.662,93.222 121.662,95.032 121.874,95.244 122.596,95.244 123.043,95.244 123.043,95.865 123.421,96.242 123.421,96.619 ; 123.021,94.519 123.021,92.365 123.028,92.365
  Top Layer w0.3: 119.039,124.228 119.039,124.728 119.039,125.128 119.039,125.528 119.039,125.928 119.039,126.328 119.039,126.728 119.039,127.128
  other v1: 113.054,81.027 115.151,81.027 117.248,81.027 119.345,81.027 121.442,81.027 123.539,81.027 125.636,81.027 127.733,81.027 129.83,81.027 131.927,81.027 134.024,81.027 136.121,81.027 171.705,82.074 171.705,84.159 171.705,86.244 126.203,87.539 171.705,88.328 171.705,90.413 171.705,92.498 114.902,92.62 171.705,94.582 130.65,95.287 130.142,95.795 171.705,96.667 132.299,97.191 131.791,97.699 131.22,98.1 117.571,98.444 171.705,98.752 171.705,100.836 171.705,102.921 171.705,105.006 171.705,107.09 171.705,109.175 171.705,111.26 171.705,113.345 171.705,115.429 171.705,117.514 171.705,119.599 107.022,120.085 171.705,121.683 171.705,123.768 171.705,125.853 171.705,127.937 114.768,128.214 101.878,140.371 103.975,140.371 106.072,140.371 108.169,140.371 110.266,140.371 112.363,140.371 114.46,140.371 116.557,140.371 118.654,140.371 120.751,140.371 122.848,140.371 124.944,140.371
  other v2: 128.896,102.643 128.983,103.785 154.2,105.78 129.763,107.565 147.283,107.925 129.138,108.369 146.623,108.525 146.143,109.365

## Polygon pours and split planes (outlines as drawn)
ISHUNT on Bottom Layer (solid, remove dead copper, pour order 76): 85.817,108.367 91.151,108.367 91.151,109.97 85.817,109.97
ADC1 on Top Layer (solid, remove dead copper, pour order 38): 85.817,112.177 91.151,112.177 91.151,113.701 85.817,113.701
no net on Top Layer (solid, remove dead copper, pour order 80): 78.06,77.58 176.34,77.58 176.34,144.6 78.06,144.6
no net on Bottom Layer (solid, remove dead copper, pour order 122): 76.2,76.2 179.16,76.2 179.16,146.64 76.2,146.64
SW on Top Layer (solid, remove dead copper): 117.624,128.701 118.557,128.701 119.04,129.184 119.929,129.184 121.237,130.492 121.237,137.243 120.4,138.204 117.341,138.204 116.924,137.699 116.924,129.28 117.478,128.984
OUT_BATT on Top Layer (solid, remove dead copper, pour order 2): 139.296,139.465 139.296,114.726 127.587,114.465 116.064,114.465 114.345,116.184 114.345,120.074 114.608,120.338 115.586,120.338 117.043,121.237 117.043,122.028 117.186,122.21 117.816,122.208 117.891,122.122 117.891,118.769 116.726,118.055 116.731,117.415 117.259,117.072 130.927,117.065 133.769,120.501 133.769,139.465
+5V on Top Layer (solid, remove dead copper, pour order 4): 123.471,107.077 127.092,106.843 127.251,103.227 127.969,101.548 127.969,96.004 127.752,95.692 127.752,95.017 127.545,94.811 126.777,94.811 126.571,95.017 126.571,97.795 123.471,100.895
SW_1 on Top Layer (solid, remove dead copper, pour order 6): 113.205,109.592 118.62,109.592 119.493,108.719 119.493,104.481 118.947,103.793 113.087,103.793 111.634,105.245 111.634,108.02
VOUT1 on Top Layer (solid, remove dead copper, pour order 8): 124.61,93.129 125.931,93.129 126.33,93.762 126.644,94.13 129.307,94.13 129.481,93.957 129.481,91.969 129.155,91.644 126.512,91.644 126.031,92.144 124.671,92.144 124.571,92.244 124.571,93.089
$2N28 on Top Layer (solid, remove dead copper, pour order 10): 149.134,139.965 154.964,139.965 155.164,139.765 155.164,131.665 154.464,130.965 149.671,130.965 149.134,131.502
$2N30 on Top Layer (solid, remove dead copper, pour order 12): 165.317,139.874 171.017,139.874 171.277,139.614 171.277,131.454 170.822,131 165.891,131 165.317,131.575
OUT_BATT1 on Bottom Layer (solid, remove dead copper, pour order 54): 157.764,135.715 157.764,137.215 157.364,137.615 163.164,137.615 163.164,123.715 162.764,123.315 160.191,123.315 160.191,126.834 159.564,127.461 157.764,127.461 157.764,135.415 157.564,135.615 157.664,135.715
$1N27791 on Bottom Layer (solid, remove dead copper, pour order 56): 135.88,120.043 136.064,120.043 136.064,120.065 135.964,120.165 135.964,120.127
$1N27791 on Bottom Layer (solid, remove dead copper, pour order 58): 136.064,118.065 141.564,118.065 141.964,117.665 141.964,110.365 141.864,110.265 135.964,110.265 135.864,110.165 135.864,117.865
$1N2164 on Bottom Layer (solid, remove dead copper, pour order 60): 155.764,117.465 161.764,117.465 161.864,117.365 161.864,110.365 161.964,110.265 155.964,110.265 155.764,110.465
OUT_BATT2 on Bottom Layer (solid, remove dead copper, pour order 62): 141.764,136.665 142.437,136.665 141.764,137.338
OUT_BATT2 on Bottom Layer (solid, remove dead copper, pour order 64): 141.702,137.681 147.795,137.681 147.795,133.497 146.145,129.002 146.145,123.154 145.185,123.17 143.827,122.589 140.676,122.552 140.264,122.965 140.264,131.265 141.702,132.703
UBATT on Bottom Layer (solid, remove dead copper, pour order 66): 135.845,103.465 135.845,101.117 139.614,97.016 155.515,97.016 157.637,99.138 157.637,104.465 155.764,104.465 155.126,103.827 155.126,100.146 153.745,98.765 141.064,98.765 138.018,101.811 138.018,102.988 137.344,103.465
OUT_BATT on Bottom Layer (solid, remove dead copper, pour order 68): 140.783,91.584 141.175,91.192 146.975,91.192 147.672,91.579 147.672,92.179 146.683,93.168 141.305,93.168 140.783,92.748
OUT_BATT on Top Layer (solid, remove dead copper, pour order 30): 142.515,91.405 142.515,92.802 142.199,93.297 140.571,93.297 139.317,94.267 139.317,116.064 131.884,115.993 130.911,114.528 133.996,110.766 134.077,94.143 137.085,91.134 142.244,91.134
+5V on Bottom Layer (solid, remove dead copper, pour order 72): 102.385,138.538 105.441,138.538 105.81,138.08 105.81,114.535 106.645,113.701 109.086,113.701 109.439,113.44 109.439,110.949 109,110.764 104.882,110.764 101.946,113.701 101.946,138.03
+5V on Top Layer (solid, remove dead copper, pour order 34): 106.264,111.281 106.264,113.343 107.026,113.701 125.53,113.701 127.263,111.968 127.263,107.523 125.949,106.208 123.917,106.208 123.409,106.716 123.409,109.891 122.52,110.78 107.036,110.78
+5V on Bottom Layer (solid, remove dead copper, pour order 80): 85.441,88.806 85.77,89.052 103.534,89.126 105.375,87.285 105.375,85.761 104.867,85.253 98.835,85.253 96.878,87.21 85.964,87.21 85.436,87.412
+5V on Top Layer (solid, remove dead copper, pour order 42): 85.436,138.085 85.944,138.593 105.704,138.593 106.251,138.046 106.251,136.294 105.629,135.672 101.922,135.672 100.525,137.069 85.817,137.069 85.436,137.45
+5V on Top Layer (solid, remove dead copper, pour order 44): 104.994,113.701 110.074,113.701 110.709,113.066 110.709,111.542 109.045,109.878 109.045,89.894 108.572,89.321 106.39,89.321 105.502,89.816 105.502,109.879 104.359,111.415
+5V on Top Layer (solid, remove dead copper, pour order 46): 85.69,96.885 86.082,97.318 104.867,97.318 106.264,98.715 106.264,94.397 106.137,94.27 104.867,95.54 86.096,95.54 85.69,95.794
VOUT1 on Bottom Layer (solid, remove dead copper, pour order 88): 131.156,90.128 130.864,89.825 118.71,89.825 104.74,103.795 86.452,103.795 85.436,104.24 85.436,105.288 86.435,105.573 105.883,105.573 119.599,91.857 130.902,91.857 131.156,91.603
+5V on Top Layer (solid, remove dead copper, pour order 50): 85.697,93.093 86.198,93.508 104.74,93.508 106.264,95.032 106.264,90.436 104.761,91.73 86.443,91.73 85.69,92.238
+5V on Bottom Layer (solid, remove dead copper, pour order 92): 107.083,91.125 108.403,91.125 108.883,90.645 108.883,87.4 106.757,85.273 101.475,85.273 101.323,85.425 101.323,87.885 102.043,88.605 103.006,88.605 105.544,91.142 107.066,91.142
no net on Bottom Layer (solid, remove dead copper, pour order 94): 147.204,120.033 147.204,120.897 cw(c147.307,120.897) 147.307,120.999 148.113,120.999 cw(c148.113,120.897) 148.216,120.897 148.216,120.033 cw(c148.113,120.033) 148.113,119.93 147.307,119.93 cw(c147.307,120.033)
no net on Bottom Layer (solid, remove dead copper, pour order 96): 132.753,120.296 132.053,120.296 cw(c132.053,120.399) 131.951,120.399 131.951,121.299 cw(c132.053,121.299) 132.053,121.401 132.753,121.401 cw(c132.753,121.299) 132.856,121.299 132.856,120.399 cw(c132.753,120.399)
no net on Bottom Layer (solid, remove dead copper, pour order 98): 147.204,120.033 147.204,120.897 cw(c147.307,120.897) 147.307,120.999 148.113,120.999 cw(c148.113,120.897) 148.216,120.897 148.216,120.033 cw(c148.113,120.033) 148.113,119.93 147.307,119.93 cw(c147.307,120.033)
no net on Bottom Layer (solid, remove dead copper, pour order 100): 132.753,120.296 132.053,120.296 cw(c132.053,120.399) 131.951,120.399 131.951,121.299 cw(c132.053,121.299) 132.053,121.401 132.753,121.401 cw(c132.753,121.299) 132.856,121.299 132.856,120.399 cw(c132.753,120.399)
no net on Bottom Layer (solid, remove dead copper, pour order 102): 147.204,120.033 147.204,120.897 cw(c147.307,120.897) 147.307,120.999 148.113,120.999 cw(c148.113,120.897) 148.216,120.897 148.216,120.033 cw(c148.113,120.033) 148.113,119.93 147.307,119.93 cw(c147.307,120.033)
no net on Bottom Layer (solid, remove dead copper, pour order 104): 132.753,120.296 132.053,120.296 cw(c132.053,120.399) 131.951,120.399 131.951,121.299 cw(c132.053,121.299) 132.053,121.401 132.753,121.401 cw(c132.753,121.299) 132.856,121.299 132.856,120.399 cw(c132.753,120.399)
no net on Bottom Layer (solid, remove dead copper, pour order 106): 147.204,120.033 147.204,120.897 cw(c147.307,120.897) 147.307,120.999 148.113,120.999 cw(c148.113,120.897) 148.216,120.897 148.216,120.033 cw(c148.113,120.033) 148.113,119.93 147.307,119.93 cw(c147.307,120.033)
no net on Bottom Layer (solid, remove dead copper, pour order 108): 131.951,120.399 131.951,121.299 cw(c132.053,121.299) 132.053,121.401 132.753,121.401 cw(c132.753,121.299) 132.856,121.299 132.856,120.399 cw(c132.753,120.399) 132.753,120.296 132.053,120.296 cw(c132.053,120.399)
+5V on Top Layer (solid, remove dead copper, pour order 70): 107.126,129.649 107.148,129.655 107.143,129.665 107.139,129.665
+5V on Top Layer (solid, remove dead copper, pour order 72): 101.88,138.18 103.02,139.32 110.22,139.32 111.06,138.48 111.06,133.378 102.338,133.378 101.88,133.846
+5V on Top Layer (solid, remove dead copper, pour order 74): 112.24,124.613 112.366,124.487 112.366,123.886 112.2,123.72 102.84,123.72 102.054,124.047 102.054,124.584 102.081,124.613
+5V on Top Layer (solid, remove dead copper, pour order 76): 85.184,130.212 98.646,130.212 99.408,129.45 99.408,126.529 100.678,125.259 104.869,125.259 105.377,124.751 105.377,123.1 104.996,122.719 100.17,122.719 97.122,125.767 97.122,128.26 96.596,128.942 85.565,128.942 85.184,129.323
+5V on Top Layer (solid, remove dead copper, pour order 78): 85.311,121.957 93.312,121.957 97.503,126.148 99.027,126.148 100.678,124.497 100.678,123.227 98.011,120.56 85.438,120.56 85.438,121.83

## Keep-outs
Board Outline Layer:
  lines w0.254: 80.864,79.665 172.864,79.665 172.864,141.665 80.864,141.665 80.864,79.665
Multi-Layer:
  circle w0.254: c97.259,134.048 r1.25
  circle w0.254: c97.276,111.161 r1.25
  region: 115.484,123.565 119.784,123.565 119.784,128.614 115.484,128.614
  region: 121.658,93.319 125.52,93.319 125.52,97.65 121.658,97.65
